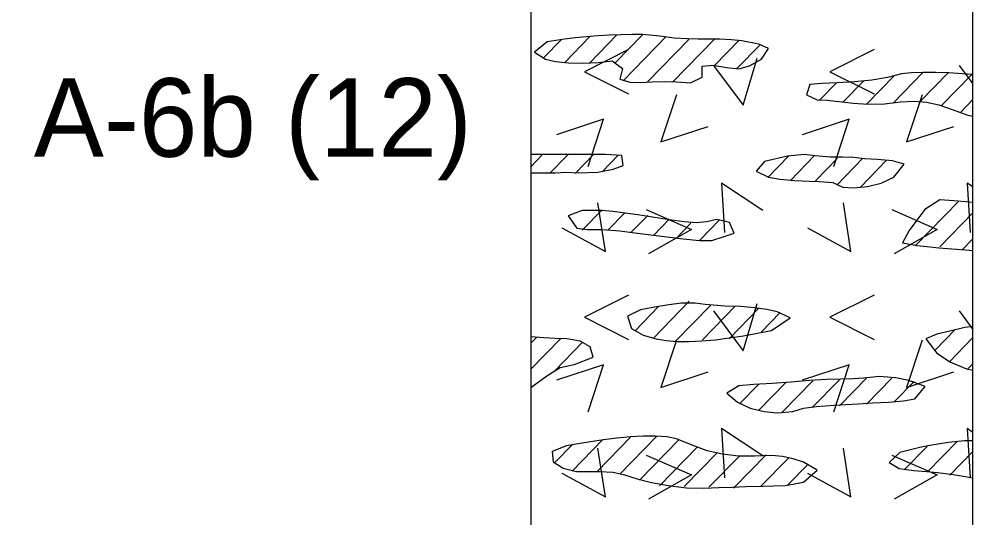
# Model space of a CAD drawing. Extents: x 0 to 0.83, y -0.65 to 1.27.
# Drawn here: x 0.7524 to 0.8333, y 0.8629 to 0.9052 of the extents above; entities that cross this region are included whole.
import ezdxf

# ---------------------------------------------------------------- set-up
doc = ezdxf.new("R2010")
doc.units = 0

msp = doc.modelspace()

# ---------------------------------------------------------------- linework, layer by layer
for points in [[(0, 0), (0.833332, 0), (0.833332, 1.274997), (0, 1.274997)], [(0, 0), (0.833332, 0), (0.833332, 1.274997), (0, 1.274997)], [(0, 0), (0.833332, 0), (0.833332, 1.274997), (0, 1.274997)], [(0, 0), (0.833332, 0), (0.833332, 1.274997), (0, 1.274997)], [(0, 0), (0.833332, 0), (0.833332, 1.274997), (0, 1.274997)], [(0.797084, 0.901809), (0.797938, 0.901631), (0.799042, 0.901519), (0.800285, 0.901485), (0.801555, 0.90154), (0.802742, 0.901694), (0.803614, 0.901032), (0.803377, 0.900135), (0.804221, 0.899865), (0.805167, 0.899846), (0.806129, 0.899902), (0.807202, 0.899933), (0.808182, 0.899902), (0.809387, 0.899828), (0.81037, 0.900294), (0.81038, 0.901241), (0.811296, 0.901304), (0.812442, 0.901116), (0.813463, 0.90101), (0.814379, 0.901266), (0.815394, 0.901809), (0.816006, 0.902721), (0.81517, 0.903094), (0.813738, 0.90337), (0.812849, 0.903463), (0.811872, 0.903521), (0.810001, 0.903523), (0.809104, 0.903541), (0.808002, 0.903615), (0.806784, 0.903772), (0.805305, 0.903903), (0.804427, 0.903916), (0.803488, 0.9039), (0.802511, 0.903859), (0.801521, 0.903797), (0.80054, 0.903719), (0.799593, 0.903628), (0.798702, 0.903529), (0.797221, 0.903306), (0.796138, 0.902428)], [(0.832407, 0.90059), (0.831293, 0.900655), (0.830172, 0.900692), (0.829096, 0.900694), (0.828115, 0.900655), (0.827281, 0.900567), (0.826083, 0.900267), (0.824762, 0.900041), (0.823296, 0.899904), (0.821831, 0.899822), (0.820509, 0.899763), (0.819505, 0.899664), (0.819224, 0.8988), (0.820125, 0.898381), (0.820967, 0.898329), (0.821997, 0.89823), (0.823181, 0.8981), (0.824476, 0.898011), (0.825838, 0.898036), (0.82719, 0.898201), (0.828356, 0.898267), (0.829402, 0.898186), (0.830435, 0.897953), (0.831559, 0.897562), (0.832909, 0.897072), (0.833332, 0.896996), (0.833332, 0.900515)], [(0.795832, 0.892177), (0.796757, 0.892167), (0.797925, 0.892187), (0.798816, 0.892225), (0.799915, 0.892182), (0.801515, 0.892226), (0.802823, 0.892483), (0.803666, 0.892802), (0.80354, 0.893641), (0.802165, 0.893726), (0.795832, 0.893726)], [(0.818216, 0.891532), (0.819444, 0.891474), (0.820325, 0.891433), (0.821453, 0.891366), (0.822286, 0.890952), (0.82324, 0.890907), (0.824378, 0.891012), (0.825554, 0.891301), (0.826624, 0.891805), (0.82749, 0.892902), (0.826513, 0.893206), (0.825239, 0.893306), (0.82413, 0.89337), (0.823236, 0.893476), (0.822257, 0.893495), (0.821211, 0.893519), (0.819948, 0.893611), (0.819024, 0.893726), (0.817611, 0.893587), (0.815663, 0.893143), (0.814958, 0.892304), (0.815983, 0.891816), (0.816947, 0.89164)], [(0.833053, 0.889678), (0.831709, 0.88979), (0.830539, 0.889891), (0.829246, 0.889071), (0.828567, 0.888157), (0.827924, 0.88727), (0.827345, 0.886244), (0.828579, 0.886018), (0.829451, 0.885917), (0.830451, 0.885821), (0.831549, 0.885725), (0.832716, 0.885629), (0.833332, 0.885577), (0.833332, 0.889669)], [(0.800664, 0.887375), (0.801881, 0.887369), (0.803392, 0.88724), (0.804229, 0.887144), (0.805103, 0.887034), (0.806004, 0.886916), (0.806919, 0.886795), (0.807838, 0.886677), (0.808747, 0.886567), (0.810142, 0.886426), (0.811186, 0.886437), (0.812223, 0.886782), (0.81308, 0.887067), (0.812673, 0.887969), (0.811597, 0.888217), (0.810749, 0.888018), (0.809892, 0.887935), (0.808847, 0.888016), (0.807995, 0.888127), (0.807033, 0.888272), (0.805997, 0.888435), (0.804922, 0.888602), (0.803843, 0.888759), (0.802797, 0.888891), (0.801817, 0.888983), (0.800202, 0.888992), (0.799007, 0.888519), (0.79974, 0.887477)], [(0.812326, 0.88087), (0.810635, 0.880989), (0.809773, 0.881122), (0.808601, 0.881129), (0.807553, 0.880985), (0.806321, 0.880786), (0.805133, 0.880543), (0.804031, 0.880022), (0.804359, 0.878961), (0.805363, 0.878394), (0.806466, 0.878096), (0.807303, 0.877945), (0.80824, 0.877869), (0.80926, 0.87786), (0.810349, 0.877911), (0.811489, 0.878014), (0.812666, 0.878161), (0.813863, 0.878344), (0.815063, 0.878557), (0.816252, 0.878791), (0.81783, 0.879872), (0.816735, 0.880371), (0.815852, 0.880574), (0.814797, 0.880731), (0.813609, 0.880834)], [(0.832654, 0.879057), (0.831362, 0.878748), (0.830275, 0.878473), (0.829339, 0.87808), (0.830265, 0.876879), (0.831418, 0.876116), (0.832792, 0.875538), (0.833332, 0.875439), (0.833332, 0.879148)], [(0.795832, 0.873961), (0.79719, 0.874951), (0.798312, 0.875653), (0.799509, 0.875924), (0.801112, 0.876525), (0.800861, 0.87741), (0.800021, 0.877885), (0.798893, 0.87808), (0.797908, 0.878109), (0.796943, 0.878166), (0.795832, 0.878249)], [(0.825375, 0.874904), (0.824078, 0.874754), (0.823187, 0.874697), (0.822142, 0.874673), (0.820907, 0.874636), (0.819474, 0.874544), (0.817918, 0.874424), (0.816318, 0.874304), (0.814751, 0.874211), (0.813476, 0.874111), (0.812472, 0.873471), (0.813366, 0.87271), (0.814436, 0.872206), (0.815612, 0.871917), (0.816749, 0.871812), (0.818067, 0.871924), (0.818959, 0.8722), (0.820031, 0.872344), (0.821573, 0.872466), (0.82253, 0.872524), (0.823615, 0.872583), (0.824832, 0.872644), (0.826183, 0.87271), (0.827451, 0.872818), (0.828416, 0.872994), (0.829268, 0.874049), (0.827909, 0.874565), (0.826788, 0.874765)], [(0.798854, 0.868996), (0.797634, 0.868535), (0.797728, 0.867639), (0.798587, 0.867115), (0.799696, 0.866819), (0.800742, 0.866829), (0.801652, 0.866843), (0.802809, 0.86676), (0.803766, 0.866552), (0.804856, 0.866203), (0.80606, 0.865906), (0.807509, 0.865632), (0.809046, 0.865446), (0.810517, 0.865416), (0.811769, 0.865473), (0.812889, 0.865514), (0.814075, 0.865549), (0.815527, 0.86559), (0.816416, 0.865615), (0.817445, 0.865647), (0.818967, 0.865921), (0.820111, 0.866956), (0.818963, 0.867625), (0.818099, 0.867893), (0.817169, 0.868089), (0.816265, 0.868194), (0.814793, 0.868135), (0.813435, 0.868138), (0.812104, 0.868288), (0.810802, 0.868591), (0.809527, 0.869051), (0.808198, 0.8696), (0.807356, 0.86976), (0.806403, 0.869835), (0.805364, 0.869835), (0.804267, 0.869775), (0.803138, 0.869666), (0.802006, 0.869521), (0.800896, 0.869353), (0.799837, 0.869174)], [(0.832629, 0.869442), (0.831261, 0.869304), (0.829688, 0.869039), (0.828826, 0.868866), (0.82712, 0.868455), (0.826226, 0.867586), (0.827084, 0.867094), (0.828308, 0.866908), (0.829408, 0.866842), (0.830335, 0.866753), (0.831655, 0.866571), (0.832526, 0.866428), (0.833332, 0.866286), (0.833332, 0.869434)]]:
    msp.add_lwpolyline(points, close=True)
for points in [[(0.795832, 1.220831), (0.795832, -0.645749)], [(0.833332, -0.645749), (0.833332, 1.133648)], [(0.79871, 0.901552), (0.800849, 0.903743)], [(0.800827, 0.901508), (0.803111, 0.903849)], [(0.805344, 0.903923), (0.802987, 0.901508)], [(0.80367, 0.899996), (0.807321, 0.903737)], [(0.798444, 0.903492), (0.796912, 0.901922)], [(0.805714, 0.899878), (0.809241, 0.903492)], [(0.811418, 0.903509), (0.807854, 0.899857)], [(0.811407, 0.901285), (0.81348, 0.90341)], [(0.815282, 0.903044), (0.813313, 0.901026)], [(0.804125, 0.90263), (0.800375, 0.900755), (0.804125, 0.89888)], [(0.824958, 0.90263), (0.821208, 0.900755), (0.824958, 0.89888)], [(0.811342, 0.901289), (0.813842, 0.897914), (0.815029, 0.901914)], [(0.832175, 0.901289), (0.833332, 0.899727)], [(0.829094, 0.900694), (0.826565, 0.898102)], [(0.828848, 0.898229), (0.831218, 0.900657)], [(0.833245, 0.900522), (0.830651, 0.897863)], [(0.820346, 0.898367), (0.821763, 0.899819)], [(0.822335, 0.898193), (0.824076, 0.899977)], [(0.824327, 0.898021), (0.82666, 0.900411)], [(0.808181, 0.898798), (0.806868, 0.894798), (0.810868, 0.896111)], [(0.829014, 0.898798), (0.827702, 0.894798), (0.831702, 0.896111)], [(0.833332, 0.898397), (0.832267, 0.897306)], [(0.800689, 0.892718), (0.802002, 0.896718), (0.798002, 0.895405)], [(0.821523, 0.892718), (0.822835, 0.896718), (0.818835, 0.895405)], [(0.795832, 0.892696), (0.796808, 0.893696)], [(0.798985, 0.893714), (0.797473, 0.892165)], [(0.801161, 0.893732), (0.799593, 0.892124)], [(0.803281, 0.893691), (0.801883, 0.892259)], [(0.817701, 0.89359), (0.815961, 0.891807)], [(0.819878, 0.893608), (0.817852, 0.891531)], [(0.821854, 0.893419), (0.819972, 0.891491)], [(0.824002, 0.893408), (0.821778, 0.891129)], [(0.826007, 0.89325), (0.823783, 0.890971)], [(0.815512, 0.888992), (0.812012, 0.891304), (0.812262, 0.887117)], [(0.833332, 0.890983), (0.832845, 0.891304), (0.833095, 0.887117)], [(0.798466, 0.887509), (0.802154, 0.885509), (0.801529, 0.889634)], [(0.8193, 0.887509), (0.822987, 0.885509), (0.822362, 0.889634)], [(0.832167, 0.889804), (0.828441, 0.885987)], [(0.801877, 0.889031), (0.800195, 0.887307)], [(0.803798, 0.888787), (0.80237, 0.887324)], [(0.805745, 0.888569), (0.804291, 0.887079)], [(0.805617, 0.889054), (0.809456, 0.887371), (0.805806, 0.885309)], [(0.82645, 0.889054), (0.83029, 0.887371), (0.826639, 0.885309)], [(0.833332, 0.888785), (0.830521, 0.885906)], [(0.80758, 0.888236), (0.806268, 0.886891)], [(0.809414, 0.887903), (0.808159, 0.886617)], [(0.811876, 0.888213), (0.810165, 0.886459)], [(0.833332, 0.886572), (0.832451, 0.88567)], [(0.804125, 0.881796), (0.800375, 0.879921), (0.804125, 0.878046)], [(0.806256, 0.878186), (0.809278, 0.881283)], [(0.811342, 0.880455), (0.813842, 0.87708), (0.815029, 0.88108)], [(0.824958, 0.881796), (0.821208, 0.879921), (0.824958, 0.878046)], [(0.804649, 0.878753), (0.806674, 0.880828)], [(0.80809, 0.877853), (0.811113, 0.880951)], [(0.810409, 0.878017), (0.813175, 0.880851)], [(0.812643, 0.878094), (0.815181, 0.880694)], [(0.815361, 0.878665), (0.816987, 0.880331)], [(0.832175, 0.880455), (0.833332, 0.878894)], [(0.830098, 0.877091), (0.831838, 0.878874)], [(0.796303, 0.878207), (0.795832, 0.877724)], [(0.798338, 0.878079), (0.795832, 0.875511)], [(0.797862, 0.875379), (0.800229, 0.877804)], [(0.808181, 0.877965), (0.806868, 0.873965), (0.810868, 0.875277)], [(0.829014, 0.877965), (0.827702, 0.873965), (0.831702, 0.875277)], [(0.831305, 0.876117), (0.833332, 0.878192)], [(0.800689, 0.871884), (0.802002, 0.875884), (0.798002, 0.874572)], [(0.821523, 0.871884), (0.822835, 0.875884), (0.818835, 0.874572)], [(0.832854, 0.87549), (0.833332, 0.875979)], [(0.819696, 0.872251), (0.822034, 0.874648)], [(0.822015, 0.872414), (0.824297, 0.874752)], [(0.824306, 0.872549), (0.826445, 0.874741)], [(0.815192, 0.874275), (0.813538, 0.872579)], [(0.815145, 0.872013), (0.817482, 0.874408)], [(0.817092, 0.871796), (0.819744, 0.874512)], [(0.826625, 0.872713), (0.828336, 0.874466)], [(0.801419, 0.866799), (0.804299, 0.869751)], [(0.806532, 0.869826), (0.803395, 0.866612)], [(0.815512, 0.868158), (0.812012, 0.870471), (0.812262, 0.866283)], [(0.833332, 0.870149), (0.832845, 0.870471), (0.833095, 0.866283)], [(0.799375, 0.869131), (0.797863, 0.867581)], [(0.799328, 0.86687), (0.801951, 0.869558)], [(0.805059, 0.866103), (0.808397, 0.869524)], [(0.809973, 0.868926), (0.806747, 0.86562)], [(0.827512, 0.866978), (0.82945, 0.868963)], [(0.832025, 0.869391), (0.829489, 0.866791)], [(0.798466, 0.866676), (0.802154, 0.864676), (0.801529, 0.868801)], [(0.805617, 0.868221), (0.809456, 0.866538), (0.805806, 0.864476)], [(0.811636, 0.868418), (0.808841, 0.865554)], [(0.813527, 0.868142), (0.810936, 0.865488)], [(0.813032, 0.865422), (0.815789, 0.868248)], [(0.8193, 0.866676), (0.822987, 0.864676), (0.822362, 0.868801)], [(0.82645, 0.868221), (0.83029, 0.866538), (0.826639, 0.864476)], [(0.831379, 0.866516), (0.833332, 0.868516)], [(0.815342, 0.865577), (0.817681, 0.867973)], [(0.817605, 0.865682), (0.819344, 0.867465)], [(0.833327, 0.866299), (0.833332, 0.866304)]]:
    msp.add_lwpolyline(points)

# ---------------------------------------------------------------- texts
msp.add_text('A-6b (12)', height=0.0066667).set_placement((0.753677, 0.89354))

doc.saveas('drawing.dxf')
